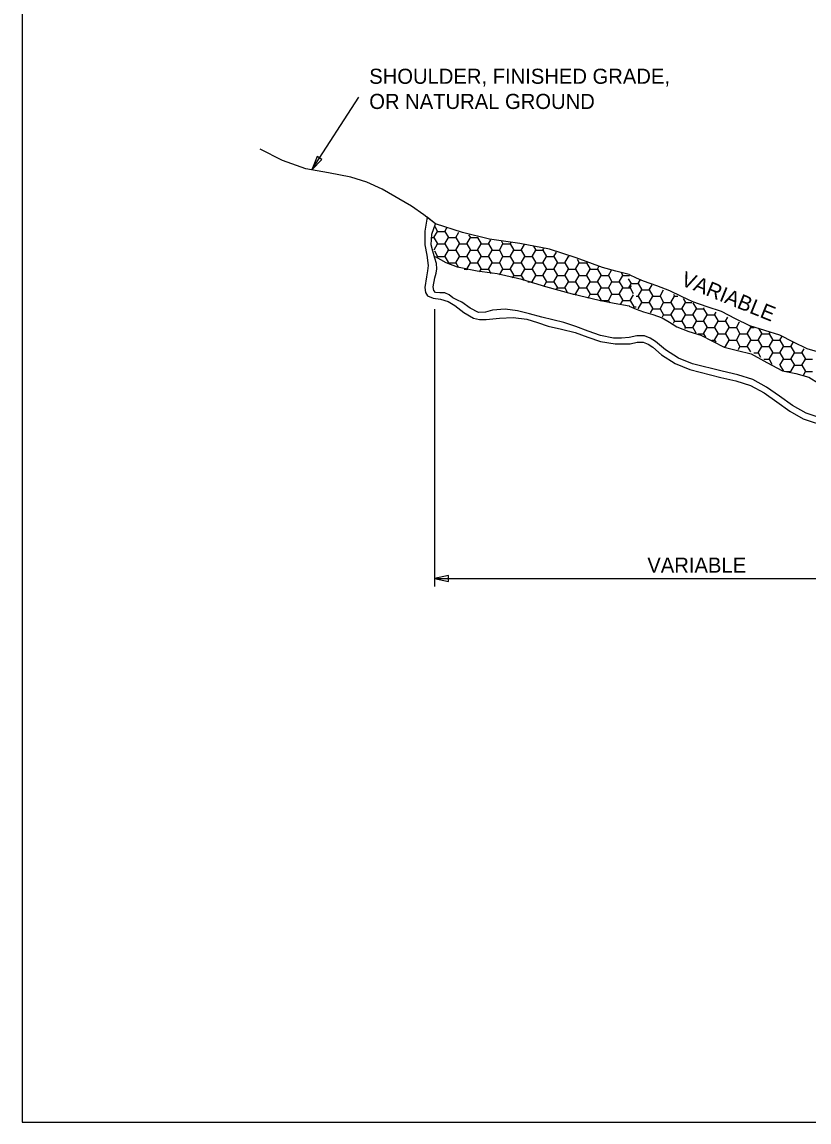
# Model space of a CAD drawing. Extents: x -439.1 to -407.9, y -458.1 to -436.2.
# Drawn here: x -439.11 to -431.29, y -458.05 to -447.12 of the extents above; entities that cross this region are included whole.
import ezdxf

# ---------------------------------------------------------------- set-up
doc = ezdxf.new("R2010")
doc.units = 0
doc.layers.add('Default', color=7, linetype='Continuous')
doc.layers.add('Draft_Named_Boundary', color=7, linetype='Continuous')

msp = doc.modelspace()

# ---------------------------------------------------------------- linework, layer by layer
at = {"layer": 'Default'}
for p, q in [((-436.229, -448.591), (-435.763, -447.872)), ((-435.001, -449.128), (-435.086, -449.063)), ((-435.008, -449.156), (-434.981, -449.204)), ((-434.909, -449.204), (-434.889, -449.169)), ((-435.037, -449.266), (-435.017, -449.266)), ((-435.017, -449.266), (-434.981, -449.204)), ((-435.017, -449.266), (-434.981, -449.329)), ((-434.981, -449.204), (-434.909, -449.204)), ((-434.909, -449.204), (-434.873, -449.266)), ((-434.909, -449.329), (-434.873, -449.266)), ((-434.873, -449.266), (-434.801, -449.266)), ((-434.801, -449.266), (-434.769, -449.212)), ((-434.801, -449.266), (-434.765, -449.329)), ((-434.692, -449.329), (-434.656, -449.266)), ((-434.673, -449.238), (-434.656, -449.266)), ((-434.656, -449.266), (-434.584, -449.266)), ((-434.584, -449.266), (-434.58, -449.259)), ((-434.584, -449.266), (-434.548, -449.329)), ((-434.476, -449.329), (-434.452, -449.287)), ((-434.347, -449.301), (-434.332, -449.329)), ((-435.015, -449.388), (-434.981, -449.329)), ((-435.013, -449.398), (-434.981, -449.454)), ((-434.981, -449.329), (-434.909, -449.329)), ((-434.909, -449.329), (-434.873, -449.391)), ((-434.909, -449.454), (-434.873, -449.391)), ((-434.873, -449.391), (-434.801, -449.391)), ((-434.801, -449.391), (-434.765, -449.329)), ((-434.801, -449.391), (-434.765, -449.454)), ((-434.765, -449.329), (-434.692, -449.329)), ((-434.692, -449.329), (-434.656, -449.391)), ((-434.692, -449.454), (-434.656, -449.391)), ((-434.656, -449.391), (-434.584, -449.391)), ((-434.584, -449.391), (-434.548, -449.329)), ((-434.584, -449.391), (-434.548, -449.454)), ((-434.548, -449.329), (-434.476, -449.329)), ((-434.476, -449.329), (-434.44, -449.391)), ((-434.476, -449.454), (-434.44, -449.391)), ((-434.44, -449.391), (-434.368, -449.391)), ((-434.368, -449.391), (-434.332, -449.329)), ((-434.368, -449.391), (-434.332, -449.454)), ((-434.332, -449.329), (-434.259, -449.329)), ((-434.259, -449.329), (-434.251, -449.315)), ((-434.259, -449.329), (-434.223, -449.391)), ((-434.259, -449.454), (-434.223, -449.391)), ((-434.223, -449.391), (-434.151, -449.391)), ((-434.151, -449.391), (-434.118, -449.333)), ((-434.151, -449.391), (-434.115, -449.454)), ((-434.043, -449.454), (-434.007, -449.391)), ((-434.03, -449.351), (-434.007, -449.391)), ((-434.007, -449.391), (-433.935, -449.391)), ((-433.935, -449.391), (-433.925, -449.374)), ((-433.935, -449.391), (-433.899, -449.454)), ((-433.826, -449.454), (-433.801, -449.41)), ((-434.987, -449.464), (-434.981, -449.454)), ((-434.981, -449.454), (-434.909, -449.454)), ((-434.909, -449.454), (-434.873, -449.516)), ((-434.874, -449.518), (-434.873, -449.516)), ((-434.873, -449.516), (-434.801, -449.516)), ((-434.801, -449.516), (-434.765, -449.454)), ((-434.801, -449.516), (-434.773, -449.564)), ((-434.765, -449.454), (-434.692, -449.454)), ((-434.692, -449.454), (-434.656, -449.516)), ((-434.692, -449.579), (-434.656, -449.516)), ((-434.656, -449.516), (-434.584, -449.516)), ((-434.584, -449.516), (-434.548, -449.454)), ((-434.584, -449.516), (-434.548, -449.579)), ((-434.548, -449.454), (-434.476, -449.454)), ((-434.476, -449.454), (-434.44, -449.516)), ((-434.476, -449.579), (-434.44, -449.516)), ((-434.44, -449.516), (-434.368, -449.516)), ((-434.368, -449.516), (-434.332, -449.454)), ((-434.368, -449.516), (-434.332, -449.579)), ((-434.332, -449.454), (-434.259, -449.454)), ((-434.259, -449.454), (-434.223, -449.516)), ((-434.259, -449.579), (-434.223, -449.516)), ((-434.223, -449.516), (-434.151, -449.516)), ((-434.151, -449.516), (-434.115, -449.454)), ((-434.151, -449.516), (-434.115, -449.579)), ((-434.115, -449.454), (-434.043, -449.454)), ((-434.043, -449.454), (-434.007, -449.516)), ((-434.043, -449.579), (-434.007, -449.516)), ((-434.007, -449.516), (-433.935, -449.516)), ((-433.935, -449.516), (-433.899, -449.454)), ((-433.935, -449.516), (-433.899, -449.579)), ((-433.899, -449.454), (-433.826, -449.454)), ((-433.826, -449.454), (-433.79, -449.516)), ((-433.826, -449.579), (-433.79, -449.516)), ((-433.79, -449.516), (-433.718, -449.516)), ((-433.718, -449.516), (-433.682, -449.454)), ((-433.718, -449.516), (-433.682, -449.579)), ((-433.684, -449.45), (-433.682, -449.454)), ((-433.682, -449.454), (-433.673, -449.454)), ((-433.61, -449.579), (-433.574, -449.516)), ((-433.595, -449.48), (-433.574, -449.516)), ((-433.574, -449.516), (-433.502, -449.516)), ((-433.502, -449.516), (-433.499, -449.512)), ((-433.502, -449.516), (-433.466, -449.579)), ((-434.716, -449.579), (-434.692, -449.579)), ((-434.692, -449.579), (-434.688, -449.586)), ((-434.564, -449.607), (-434.548, -449.579)), ((-434.548, -449.579), (-434.476, -449.579)), ((-434.476, -449.579), (-434.451, -449.622)), ((-434.365, -449.636), (-434.332, -449.579)), ((-434.332, -449.579), (-434.259, -449.579)), ((-434.259, -449.579), (-434.223, -449.641)), ((-434.151, -449.641), (-434.115, -449.579)), ((-434.115, -449.579), (-434.043, -449.579)), ((-434.043, -449.579), (-434.007, -449.641)), ((-433.935, -449.641), (-433.899, -449.579)), ((-433.899, -449.579), (-433.826, -449.579)), ((-433.826, -449.579), (-433.79, -449.641)), ((-433.718, -449.641), (-433.682, -449.579)), ((-433.682, -449.579), (-433.61, -449.579)), ((-433.61, -449.579), (-433.574, -449.641)), ((-433.502, -449.641), (-433.466, -449.579)), ((-433.466, -449.579), (-433.393, -449.579)), ((-433.393, -449.579), (-433.379, -449.553)), ((-433.393, -449.579), (-433.357, -449.641)), ((-433.285, -449.641), (-433.254, -449.588)), ((-433.157, -449.613), (-433.141, -449.641)), ((-434.237, -449.665), (-434.223, -449.641)), ((-434.223, -449.641), (-434.151, -449.641)), ((-434.151, -449.641), (-434.122, -449.692)), ((-434.084, -449.704), (-434.043, -449.704)), ((-434.043, -449.704), (-434.007, -449.641)), ((-434.043, -449.704), (-434.034, -449.719)), ((-434.007, -449.641), (-433.935, -449.641)), ((-433.935, -449.641), (-433.899, -449.704)), ((-433.927, -449.752), (-433.899, -449.704)), ((-433.899, -449.704), (-433.826, -449.704)), ((-433.826, -449.704), (-433.79, -449.641)), ((-433.826, -449.704), (-433.79, -449.766)), ((-433.79, -449.641), (-433.718, -449.641)), ((-433.718, -449.641), (-433.682, -449.704)), ((-433.718, -449.766), (-433.682, -449.704)), ((-433.682, -449.704), (-433.61, -449.704)), ((-433.61, -449.704), (-433.574, -449.641)), ((-433.61, -449.704), (-433.574, -449.766)), ((-433.574, -449.641), (-433.502, -449.641)), ((-433.502, -449.641), (-433.466, -449.704)), ((-433.502, -449.766), (-433.466, -449.704)), ((-433.466, -449.704), (-433.393, -449.704)), ((-433.393, -449.704), (-433.357, -449.641)), ((-433.393, -449.704), (-433.357, -449.766)), ((-433.357, -449.641), (-433.285, -449.641)), ((-433.285, -449.641), (-433.249, -449.704)), ((-433.285, -449.766), (-433.249, -449.704)), ((-433.249, -449.704), (-433.177, -449.704)), ((-433.177, -449.704), (-433.141, -449.641)), ((-433.177, -449.704), (-433.141, -449.766)), ((-433.141, -449.641), (-433.076, -449.641)), ((-433.087, -449.676), (-433.06, -449.722)), ((-433.086, -449.767), (-433.06, -449.722)), ((-433.069, -449.766), (-433.054, -449.742)), ((-433.06, -449.722), (-432.988, -449.722)), ((-432.988, -449.722), (-432.966, -449.683)), ((-432.988, -449.722), (-432.952, -449.784)), ((-432.88, -449.784), (-432.851, -449.734)), ((-433.802, -449.786), (-433.79, -449.766)), ((-433.79, -449.766), (-433.718, -449.766)), ((-433.718, -449.766), (-433.69, -449.814)), ((-433.635, -449.829), (-433.61, -449.829)), ((-433.61, -449.829), (-433.574, -449.766)), ((-433.61, -449.829), (-433.606, -449.836)), ((-433.574, -449.766), (-433.502, -449.766)), ((-433.502, -449.766), (-433.466, -449.829)), ((-433.487, -449.867), (-433.466, -449.829)), ((-433.466, -449.829), (-433.393, -449.829)), ((-433.393, -449.829), (-433.357, -449.766)), ((-433.393, -449.829), (-433.357, -449.891)), ((-433.357, -449.766), (-433.285, -449.766)), ((-433.285, -449.766), (-433.249, -449.829)), ((-433.285, -449.891), (-433.249, -449.829)), ((-433.249, -449.829), (-433.177, -449.829)), ((-433.177, -449.829), (-433.141, -449.766)), ((-433.177, -449.829), (-433.141, -449.891)), ((-433.141, -449.766), (-433.069, -449.766)), ((-433.069, -449.766), (-433.038, -449.82)), ((-433.069, -449.891), (-433.035, -449.833)), ((-433.01, -449.847), (-432.988, -449.847)), ((-432.988, -449.847), (-432.952, -449.784)), ((-432.988, -449.847), (-432.952, -449.909)), ((-432.952, -449.784), (-432.88, -449.784)), ((-432.88, -449.784), (-432.844, -449.847)), ((-432.88, -449.909), (-432.844, -449.847)), ((-432.844, -449.847), (-432.772, -449.847)), ((-432.772, -449.847), (-432.736, -449.785)), ((-432.772, -449.847), (-432.736, -449.909)), ((-432.664, -449.909), (-432.627, -449.847)), ((-432.638, -449.828), (-432.627, -449.847)), ((-432.627, -449.847), (-432.596, -449.847)), ((-433.361, -449.898), (-433.357, -449.891)), ((-433.357, -449.891), (-433.285, -449.891)), ((-433.285, -449.891), (-433.273, -449.913)), ((-433.164, -449.931), (-433.141, -449.891)), ((-433.141, -449.891), (-433.069, -449.891)), ((-433.077, -449.944), (-433.075, -449.946)), ((-433.069, -449.891), (-433.033, -449.954)), ((-433.037, -449.962), (-433.033, -449.954)), ((-433.033, -449.954), (-433.009, -449.954)), ((-432.988, -449.972), (-432.952, -449.909)), ((-432.952, -449.909), (-432.88, -449.909)), ((-432.88, -449.909), (-432.844, -449.972)), ((-432.772, -449.972), (-432.736, -449.909)), ((-432.736, -449.909), (-432.664, -449.909)), ((-432.664, -449.909), (-432.627, -449.972)), ((-432.555, -449.972), (-432.519, -449.909)), ((-432.541, -449.871), (-432.519, -449.909)), ((-432.519, -449.909), (-432.455, -449.909)), ((-432.445, -449.914), (-432.411, -449.972)), ((-432.339, -449.972), (-432.332, -449.96)), ((-435.013, -449.978), (-435.013, -452.73)), ((-432.99, -449.972), (-432.988, -449.972)), ((-432.988, -449.972), (-432.988, -449.973)), ((-432.867, -450.012), (-432.844, -449.972)), ((-432.844, -449.972), (-432.772, -449.972)), ((-432.772, -449.972), (-432.736, -450.034)), ((-432.746, -450.053), (-432.736, -450.034)), ((-432.736, -450.034), (-432.664, -450.034)), ((-432.664, -450.034), (-432.627, -449.972)), ((-432.664, -450.034), (-432.627, -450.097)), ((-432.627, -449.972), (-432.555, -449.972)), ((-432.555, -449.972), (-432.519, -450.034)), ((-432.555, -450.097), (-432.519, -450.034)), ((-432.519, -450.034), (-432.447, -450.034)), ((-432.447, -450.034), (-432.411, -449.972)), ((-432.447, -450.034), (-432.411, -450.097)), ((-432.411, -449.972), (-432.339, -449.972)), ((-432.339, -449.972), (-432.303, -450.034)), ((-432.339, -450.097), (-432.303, -450.034)), ((-432.303, -450.034), (-432.231, -450.034)), ((-432.231, -450.034), (-432.215, -450.008)), ((-432.231, -450.034), (-432.194, -450.097)), ((-432.122, -450.097), (-432.098, -450.055)), ((-432.638, -450.115), (-432.627, -450.097)), ((-432.627, -450.097), (-432.555, -450.097)), ((-432.555, -450.097), (-432.519, -450.159)), ((-432.525, -450.169), (-432.519, -450.159)), ((-432.519, -450.159), (-432.447, -450.159)), ((-432.447, -450.159), (-432.411, -450.097)), ((-432.447, -450.159), (-432.416, -450.212)), ((-432.411, -450.097), (-432.339, -450.097)), ((-432.339, -450.097), (-432.303, -450.159)), ((-432.339, -450.222), (-432.303, -450.159)), ((-432.303, -450.159), (-432.231, -450.159)), ((-432.231, -450.159), (-432.194, -450.097)), ((-432.231, -450.159), (-432.194, -450.222)), ((-432.194, -450.097), (-432.122, -450.097)), ((-432.122, -450.097), (-432.086, -450.159)), ((-432.122, -450.222), (-432.086, -450.159)), ((-432.086, -450.159), (-432.014, -450.159)), ((-432.014, -450.159), (-431.982, -450.103)), ((-432.014, -450.159), (-431.978, -450.222)), ((-431.906, -450.222), (-431.87, -450.159)), ((-431.877, -450.146), (-431.87, -450.159)), ((-431.87, -450.159), (-431.837, -450.159)), ((-431.79, -450.173), (-431.761, -450.222)), ((-432.393, -450.222), (-432.339, -450.222)), ((-432.339, -450.222), (-432.32, -450.255)), ((-432.259, -450.284), (-432.231, -450.284)), ((-432.231, -450.284), (-432.194, -450.222)), ((-432.231, -450.284), (-432.219, -450.304)), ((-432.194, -450.222), (-432.122, -450.222)), ((-432.122, -450.222), (-432.086, -450.284)), ((-432.122, -450.347), (-432.086, -450.284)), ((-432.086, -450.284), (-432.014, -450.284)), ((-432.014, -450.284), (-431.978, -450.222)), ((-432.014, -450.284), (-431.978, -450.347)), ((-431.978, -450.222), (-431.906, -450.222)), ((-431.906, -450.222), (-431.87, -450.284)), ((-431.906, -450.347), (-431.87, -450.284)), ((-431.87, -450.284), (-431.798, -450.284)), ((-431.798, -450.284), (-431.761, -450.222)), ((-431.798, -450.284), (-431.761, -450.347)), ((-431.761, -450.222), (-431.689, -450.222)), ((-431.689, -450.222), (-431.679, -450.205)), ((-431.689, -450.222), (-431.653, -450.284)), ((-431.689, -450.347), (-431.653, -450.284)), ((-431.653, -450.284), (-431.581, -450.284)), ((-431.581, -450.284), (-431.559, -450.246)), ((-431.581, -450.284), (-431.545, -450.347)), ((-432.13, -450.347), (-432.122, -450.347)), ((-432.122, -450.347), (-432.121, -450.349)), ((-431.994, -450.376), (-431.978, -450.347)), ((-431.978, -450.347), (-431.906, -450.347)), ((-431.906, -450.347), (-431.875, -450.401)), ((-431.798, -450.409), (-431.761, -450.347)), ((-431.761, -450.347), (-431.689, -450.347)), ((-431.689, -450.347), (-431.653, -450.409)), ((-431.581, -450.409), (-431.545, -450.347)), ((-431.545, -450.347), (-431.473, -450.347)), ((-431.473, -450.347), (-431.45, -450.308)), ((-431.473, -450.347), (-431.437, -450.409)), ((-431.365, -450.409), (-431.341, -450.369)), ((-431.841, -450.409), (-431.798, -450.409)), ((-431.798, -450.409), (-431.773, -450.452)), ((-431.741, -450.472), (-431.689, -450.472)), ((-431.689, -450.472), (-431.653, -450.409)), ((-431.689, -450.472), (-431.66, -450.522)), ((-431.653, -450.409), (-431.581, -450.409)), ((-431.581, -450.409), (-431.545, -450.472)), ((-431.581, -450.534), (-431.545, -450.472)), ((-431.545, -450.472), (-431.473, -450.472)), ((-431.473, -450.472), (-431.437, -450.409)), ((-431.473, -450.472), (-431.437, -450.534)), ((-431.437, -450.409), (-431.365, -450.409)), ((-431.365, -450.409), (-431.328, -450.472)), ((-431.365, -450.534), (-431.328, -450.472)), ((-431.328, -450.472), (-431.256, -450.472)), ((-431.581, -450.534), (-431.547, -450.593)), ((-431.52, -450.597), (-431.473, -450.597)), ((-431.473, -450.597), (-431.437, -450.534)), ((-431.473, -450.597), (-431.471, -450.6)), ((-431.437, -450.534), (-431.365, -450.534)), ((-431.365, -450.534), (-431.328, -450.597)), ((-431.348, -450.631), (-431.328, -450.597)), ((-431.328, -450.597), (-431.256, -450.597)), ((-435.013, -452.652), (-429.64, -452.652))]:
    msp.add_line(p, q, dxfattribs=at)
for points in [[(-435.001, -449.128), (-435.118, -449.038), (-435.24, -448.954), (-435.531, -448.784), (-435.684, -448.716), (-435.843, -448.666), (-436.066, -448.623), (-436.29, -448.581), (-436.523, -448.499), (-436.744, -448.388)], [(-435.086, -449.063), (-435.108, -449.202), (-435.107, -449.337), (-435.089, -449.441), (-435.076, -449.542), (-435.081, -449.597), (-435.092, -449.655), (-435.107, -449.763), (-435.102, -449.81), (-435.082, -449.844), (-435.024, -449.867), (-434.952, -449.877), (-434.877, -449.9), (-434.811, -449.939), (-434.72, -450.01), (-434.624, -450.067), (-434.564, -450.079), (-434.5, -450.079), (-434.368, -450.065), (-434.23, -450.059), (-434.096, -450.077), (-433.99, -450.109), (-433.884, -450.145), (-433.75, -450.175), (-433.616, -450.207), (-433.49, -450.254), (-433.364, -450.299), (-433.217, -450.322), (-433.067, -450.321)], [(-433.078, -450.259), (-433.156, -450.266), (-433.233, -450.264), (-433.362, -450.238), (-433.487, -450.194), (-433.607, -450.149), (-433.729, -450.11), (-433.837, -450.083), (-433.947, -450.057), (-434.067, -450.023), (-434.187, -449.992), (-434.31, -449.976), (-434.435, -449.987), (-434.507, -450.005), (-434.575, -450.01), (-434.657, -449.966), (-434.739, -449.907), (-434.784, -449.886), (-434.829, -449.864), (-434.867, -449.834), (-434.909, -449.813), (-434.958, -449.814), (-435.001, -449.812), (-435.019, -449.79), (-435.024, -449.754), (-435.01, -449.666), (-434.996, -449.619), (-434.988, -449.576), (-434.992, -449.523), (-435.007, -449.469), (-435.03, -449.402), (-435.045, -449.336), (-435.038, -449.23), (-435.001, -449.128)], [(-433.078, -449.633), (-433.211, -449.6), (-433.342, -449.563), (-433.606, -449.467), (-433.871, -449.379), (-434.166, -449.325), (-434.465, -449.281), (-434.735, -449.214), (-435.001, -449.128)], [(-433.078, -449.946), (-433.227, -449.919), (-433.375, -449.89), (-433.641, -449.828), (-433.905, -449.755), (-434.145, -449.682), (-434.389, -449.625), (-434.589, -449.6), (-434.785, -449.561), (-434.896, -449.516), (-435.001, -449.458)], [(-433.078, -449.633), (-433.008, -449.666), (-432.938, -449.696), (-432.807, -449.743), (-432.677, -449.792), (-432.563, -449.848), (-432.448, -449.901), (-432.306, -449.949), (-432.165, -449.997), (-432.024, -450.069), (-431.883, -450.139), (-431.734, -450.185), (-431.585, -450.232), (-431.449, -450.3), (-431.313, -450.366), (-431.165, -450.409)], [(-433.078, -449.946), (-433.008, -449.976), (-432.937, -450.003), (-432.842, -450.029), (-432.75, -450.062), (-432.677, -450.107), (-432.605, -450.152), (-432.486, -450.197), (-432.365, -450.236), (-432.25, -450.296), (-432.134, -450.354), (-432.001, -450.387), (-431.867, -450.42), (-431.712, -450.507), (-431.555, -450.589), (-431.423, -450.617), (-431.293, -450.651), (-431.197, -450.712)], [(-429.63, -451.655), (-429.74, -451.577), (-429.846, -451.519), (-430.076, -451.45), (-430.31, -451.393), (-430.576, -451.278), (-430.841, -451.158), (-431.084, -451.09), (-431.322, -451.01), (-431.457, -450.932), (-431.585, -450.841), (-431.714, -450.751), (-431.85, -450.676), (-431.999, -450.628), (-432.155, -450.594), (-432.45, -450.52), (-432.589, -450.462), (-432.718, -450.38), (-432.818, -450.297), (-432.87, -450.264), (-432.926, -450.243), (-433.002, -450.241), (-433.078, -450.259)], [(-433.067, -450.321), (-432.998, -450.304), (-432.939, -450.304), (-432.89, -450.323), (-432.845, -450.354), (-432.757, -450.429), (-432.622, -450.515), (-432.477, -450.577), (-432.167, -450.656), (-432.018, -450.688), (-431.875, -450.734), (-431.739, -450.808), (-431.611, -450.898), (-431.483, -450.989), (-431.349, -451.067), (-431.108, -451.147), (-430.862, -451.217), (-430.596, -451.337), (-430.329, -451.453), (-430.098, -451.508), (-429.872, -451.576), (-429.772, -451.631), (-429.654, -451.714)]]:
    msp.add_lwpolyline(points, dxfattribs=at)
for points in [[(-436.178, -448.459), (-436.229, -448.591), (-436.13, -448.491)], [(-436.178, -448.459), (-436.229, -448.591), (-436.13, -448.491)], [(-434.874, -452.623), (-435.013, -452.652), (-434.874, -452.681)]]:
    msp.add_lwpolyline(points, close=True, dxfattribs=at)
at = {"layer": 'Draft_Named_Boundary'}
msp.add_lwpolyline([(-439.109, -458.051), (-407.859, -458.051), (-407.859, -437.676), (-439.109, -437.676)], close=True, dxfattribs=at)

# ---------------------------------------------------------------- texts
at = {"layer": 'Default'}
for s, p in [('SHOULDER, FINISHED GRADE,', (-435.66, -447.738)), ('OR NATURAL GROUND', (-435.66, -447.988)), ('VARIABLE', (-432.898, -452.594))]:
    msp.add_text(s, height=0.15, dxfattribs=at).set_placement(p)
msp.add_text('VARIABLE', height=0.15, rotation=338, dxfattribs=at).set_placement((-432.575, -449.735))

doc.saveas('drawing.dxf')
